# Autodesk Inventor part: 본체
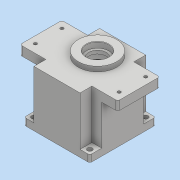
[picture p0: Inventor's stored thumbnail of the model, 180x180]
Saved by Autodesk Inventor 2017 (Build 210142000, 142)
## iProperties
Part Number: 본체
Material: 일반
Document SubType Name: Modeling
Designer: user
Density: 1 g/cm^3
Appearance: 기본값
Author: user
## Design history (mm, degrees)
sketch "스케치1"
  geometry: L1 (37, 47)-(103, 47); L2 (103, 47)-(103, 30); L3 (103, 30)-(140, 30); L4 (140, 30)-(140, -30); L5 (140, -30)-(103, -30); L6 (103, -30)-(103, -47); L7 (103, -47)-(37, -47); L8 (37, -47)-(37, -30); L9 (37, -30)-(0, -30); L10 (0, -30)-(0, 30); L11 (0, 30)-(37, 30); L12 (37, 30)-(37, 47); 1 further point
  constraints: 24 end point, 4 parallel, 3 horizontal, 3 vertical, 2 collinear, 2 midpoint, 2 perpendicular, 1 point on line
  dimensions: "d0" = 66 distance of L1.start L1.end; "d1" = 140 distance between parallel lines of L10 L4; "d2" = 66 distance of L6.end L7.end; "d3" = 37 distance between parallel lines of L10 L12; "d4" = 94 distance between parallel lines of L7 L1; "d5" = 60 distance between parallel lines of L5 L3; "d6" = 17 distance of L1.end L2.end
extrude "돌출1" new body sketch "스케치1" distance "d7" = 13; taper "d8" = 0 deg
sketch "스케치2"
  geometry: L1 (-103, -47)-(-103, -30); L2 (-103, -30)-(-117, -30); L3 (-117, -30)-(-117, 30); L4 (-117, 30)-(-103, 30); L5 (-103, 30)-(-103, 47); L6 (-103, 47)-(-37, 47); L7 (-37, 47)-(-37, 30); L8 (-37, 30)-(-23, 30); L9 (-23, 30)-(-23, -30); L10 (-23, -30)-(-37, -30); L11 (-37, -30)-(-37, -47); L12 (-37, -47)-(-103, -47); 9 further points
  constraints: 25 end point, 8 coincident, 4 perpendicular, 3 point on line, 2 parallel, 1 horizontal
  dimensions: "d9" = 94 distance between parallel lines of L9 L3; "d10" = 14 distance of L1.end L2.end
extrude "돌출2" join sketch "스케치2" distance "d11" = 57; taper "d12" = 0 deg
sketch "스케치3"
  geometry: L1 (-117, 47)-(-23, 47); L2 (-23, 47)-(-23, -47); L3 (-23, -47)-(-117, -47); L4 (-117, -47)-(-117, 47); L5 (-117, 47)-(-23, -47); L6 (-23, 47)-(-117, -47); L7 (-103, -47)-(-37, -47) reference; L8 (-23, -30)-(-23, 30) reference; 2 further points
  constraints: 12 end point, 2 collinear, 2 midpoint, 2 parallel, 1 horizontal, 1 perpendicular
  dimensions: "d13" = 94 distance of L2.end L3.end; "d14" = 94 distance of L3.end L1.start
extrude "돌출3" join sketch "스케치3" distance "d15" = 10; taper "d16" = 0 deg
sketch "스케치4"
  geometry: L1 (0, -30)-(0, 30) reference; L2 (-23, -47)-(-23, 47) reference; C1 r 43 at (-70, 0); 2 further points
  constraints: 1 centre point, 1 coincident, 1 horizontal alignment, 1 midpoint
  dimensions: "d17" = 86 diameter of C1; "d18" = 47 distance from line of C1.centre L2
extrude "돌출4" cut sketch "스케치4" distance "d19" = 9; taper "d20" = 0 deg
sketch "스케치5"
  geometry: C1 r 40 at (0, 0); C2 r 43 at (0, 0) reference; 1 further point
  constraints: 1 centre point, 1 concentric
  dimensions: "d21" = 80 diameter of C1
extrude "돌출5" cut sketch "스케치5" distance "d22" = 62; taper "d23" = 0 deg
sketch "스케치6"
  geometry: L1 (37, -47)-(103, -47) reference; C1 r 40 at (70, 0) reference; C2 r 43 at (70, 0) reference; C3 r 27.5 at (70, 11); 1 further point
  constraints: 1 centre point, 1 vertical alignment
  dimensions: "d24" = 55 diameter of C3; "d25" = 58 distance from line of L1 C3.centre
extrude "돌출6" join sketch "스케치6" distance "d26" = 7; taper "d27" = 0 deg
sketch "스케치7"
  geometry: C1 r 16 at (0, 0); C2 r 27.5 at (0, 0) reference; 1 further point
  constraints: 1 centre point, 1 concentric
  dimensions: "d28" = 32 diameter of C1
extrude "돌출7" cut sketch "스케치7" distance "d29" = 8.3; taper "d30" = 0 deg
sketch "스케치8"
  geometry: C1 r 12.5 at (0, 0); C2 r 16 at (0, 0) reference; 1 further point
  constraints: 1 centre point, 1 concentric
  dimensions: "d31" = 25 diameter of C1
extrude "돌출8" cut sketch "스케치8" distance "d32" = 4.7; taper "d33" = 0 deg
sketch "스케치10"
  geometry: C1 r 17.5 at (0, 0); C2 r 16 at (0, 0) reference; C3 r 27.5 at (0, 0) reference; 1 further point
  constraints: 1 centre point, 1 coincident
  dimensions: "d34" = 35 diameter of C1
extrude "돌출9" cut sketch "스케치10" distance "d35" = 10; taper "d36" = 0 deg
node "작업 평면2"
sketch "스케치14"
  geometry: C1 r 21 at (0, 11); C2 r 15 at (0, -20); C3 r 40 at (0, 0) reference; 1 further point
  constraints: 2 centre point, 2 vertical alignment
  dimensions: "d42" = 42 diameter of C1; "d43" = 30 diameter of C2; "d44" = 11 distance of C3.centre C1.centre; "d45" = 20 distance of C2.centre C3.centre
extrude "돌출11" join sketch "스케치14" distance "d46" = 7; taper "d47" = 0 deg
sketch "스케치15"
  geometry: L1 (33, 36)-(33, 19) reference; L2 (33, 19)-(70, 19) reference; L3 (70, 19)-(70, -41) reference; L4 (70, -41)-(33, -41) reference; L5 (33, -41)-(33, -58) reference; L6 (33, -58)-(-33, -58) reference; L7 (-33, -58)-(-33, -41) reference; L8 (-33, -41)-(-70, -41) reference; L9 (-70, -41)-(-70, 19) reference; L10 (-70, 19)-(-33, 19) reference; L11 (-33, 19)-(-33, 36) reference; L12 (-33, 36)-(33, 36) reference; C1 r 16 at (0, 0) reference; C2 r 40 at (0, -11) reference; A1 r 21 centre (0, 0) between (8.978, -18.984) and (-8.978, -18.984) reference; A2 r 15 centre (0, -31) between (-8.978, -18.984) and (8.978, -18.984) reference; 1 further point
extrude "돌출12" cut sketch "스케치15" distance "d48" = 33.75; taper "d49" = 0 deg
sketch "스케치16"
  geometry: C1 r 11 at (0, -20); A1 r 15 centre (0, -20) between (-8.978, -7.984) and (8.978, -7.984) reference; 1 further point
  constraints: 1 centre point, 1 coincident, 1 concentric
  dimensions: "d50" = 22 diameter of C1
extrude "돌출13" cut sketch "스케치16" distance "d51" = 7; taper "d52" = 0 deg
sketch "스케치17"
  geometry: C1 r 11 at (0, 0) reference; C2 r 9.5 at (0, 0); 1 further point
  constraints: 1 centre point, 1 concentric
  dimensions: "d53" = 19 diameter of C2
extrude "돌출14" cut sketch "스케치17" distance "d54" = 3; taper "d55" = 0 deg
sketch "스케치19"
  geometry: L1 (140, 30)-(140, -30) reference; L2 (117, 30)-(140, 30) reference; C1 r 2.25 at (130, -18); C2 r 2.25 at (130, 20); C3 r 16 at (70, 11) reference; 1 further point
  constraints: 2 centre point, 1 vertical alignment
  dimensions: "d58" = 4.5 diameter of C1; "d59" = 4.5 diameter of C2; "d61" = 38 distance of C1.centre C2.centre; "d64" = 10 distance from line of L1 C2.centre; "d65" = 10 distance from line of L2 C2.centre
extrude "돌출15" cut sketch "스케치19" distance "d66" = 8; taper "d67" = 0 deg
sketch "스케치20"
  geometry: C1 r 2.25 at (-130, 20) reference; C2 r 2.25 at (-130, -18) reference; C3 r 5 at (-130, -18); C4 r 5 at (-130, 20); 1 further point
  constraints: 2 centre point, 2 concentric
  dimensions: "d68" = 10 diameter of C3; "d69" = 10 diameter of C4
extrude "돌출16" cut sketch "스케치20" distance "d70" = 5; taper "d71" = 0 deg
node "작업 평면3"
sketch "스케치23"
  geometry: L1 (117, -47)-(23, -47) reference; L2 (117, 47)-(117, -47) reference; C1 r 3.5 at (110, 40); C2 r 3.5 at (110, -40); C3 r 16 at (70, 11) reference; C4 r 27.5 at (70, 11) reference; 1 further point
  constraints: 2 centre point, 1 vertical alignment
  dimensions: "d77" = 7 diameter of C1; "d78" = 7 diameter of C2; "d79" = 80 distance of C2.centre C1.centre; "d80" = 7 distance from line of L1 C2.centre; "d81" = 7 distance from line of L2 C2.centre
extrude "돌출17" cut sketch "스케치23" distance "d82" = 10; taper "d83" = 0 deg
node "작업 평면4"
sketch "스케치24"
  geometry: A1 r 40 centre (0, 0) between (39.279, 7.559) and (39.279, -7.559) reference; A2 r 4 centre (36, 0) between (36.19, 3.995) and (36.19, -3.995); A3 r 3 centre (36.333, 6.992) between (36.19, 3.995) and (39.279, 7.559); A4 r 3 centre (36.333, -6.992) between (39.279, -7.559) and (36.19, -3.995); 1 further point
  constraints: 8 point on circle, 4 tangent, 3 centre point, 1 horizontal alignment
  dimensions: "d85" = 8 diameter of A2; "d86" = 36 distance of A1.centre A2.centre; "d87" = 3 radius of A3; "d88" = 3 radius of A4
extrude "돌출18" join sketch "스케치24" stored distance "d89" = 0; taper "d90" = 0 deg
chamfer "모따기1" distance "d91" = 0.8; stored, may be unused: second distance "d92" = 2, angle "d93" = 30 deg
sketch "스케치26" dims "d4" = 94
  geometry: L1 (-14, 80)-(80, 80) reference; L2 (5.5, -7)-(60.5, -7) reference; L3 (60.5, 0)-(5.5, 0) reference; L4 (0, 70)-(0, 0) reference; 2 further points
  constraints: 1 other
  dimensions: "d97" = 40 distance from line of L1 point (33, 40); "d98" = 33 distance from line of L4 point (33, 40)
feature "엠보싱1" sketch "스케치26" dims "d99" = 0.5, "d100" = 0
hole "구멍1" diameter "d103" = 3.242; stored, may be unused: countersink angle "d107" = 90 deg, drill point angle "d109" = 118 deg; dims "d101" = 10, "d102" = 10, "d104" = 7, "d105" = 4, "d106" = 2, "d108" = 9
fillet "모깎기1" dims "d110" = 3
chamfer "모따기2" distance "d111" = 1; stored, may be unused: second distance "d112" = 2, angle "d113" = 30 deg
chamfer "모따기3" distance "d114" = 1; stored, may be unused: second distance "d115" = 2, angle "d116" = 30 deg
fillet "모깎기2" dims "d117" = 3
node "솔리드1"
mirror "미러1"
mirror "미러2"
mirror "미러3"
mirror "미러5"
node "투영된 루프1"
node "투영된 루프2"
node "투영된 루프3"
node "절단 모서리 투영1"
other parameters: "d37" = 0
